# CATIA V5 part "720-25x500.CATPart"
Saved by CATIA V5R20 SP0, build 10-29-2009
Part number: 720-25x500
Definition: NONE
Nomenclature: 720-25x500
Source: Unknown
Description: 720-25x500
Bounding box of the stored display mesh (mm): x 0 to 500, y -12.5 to 12.5, z -12.5 to 12.5
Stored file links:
  C:\Users\Utente\Desktop\IO LAVORO\3D X SITO CF\X SITO\720\720-25x500.CATPart
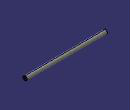
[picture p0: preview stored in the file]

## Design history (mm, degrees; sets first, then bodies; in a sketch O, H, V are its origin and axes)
Body1 "720-25x500" (main body)
  Solid1: solid without history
